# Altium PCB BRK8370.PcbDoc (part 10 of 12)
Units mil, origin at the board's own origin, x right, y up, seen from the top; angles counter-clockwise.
Board outline 8267.72 x 5708.66 mil, 6 copper layers (L1-TOP, L2-GND, L3-PWR, L4-PWR, L5-GND, L6-BOT), stack 68.606 mil thick; 319 components, 516 nets, 2008 pads, 1743 vias.
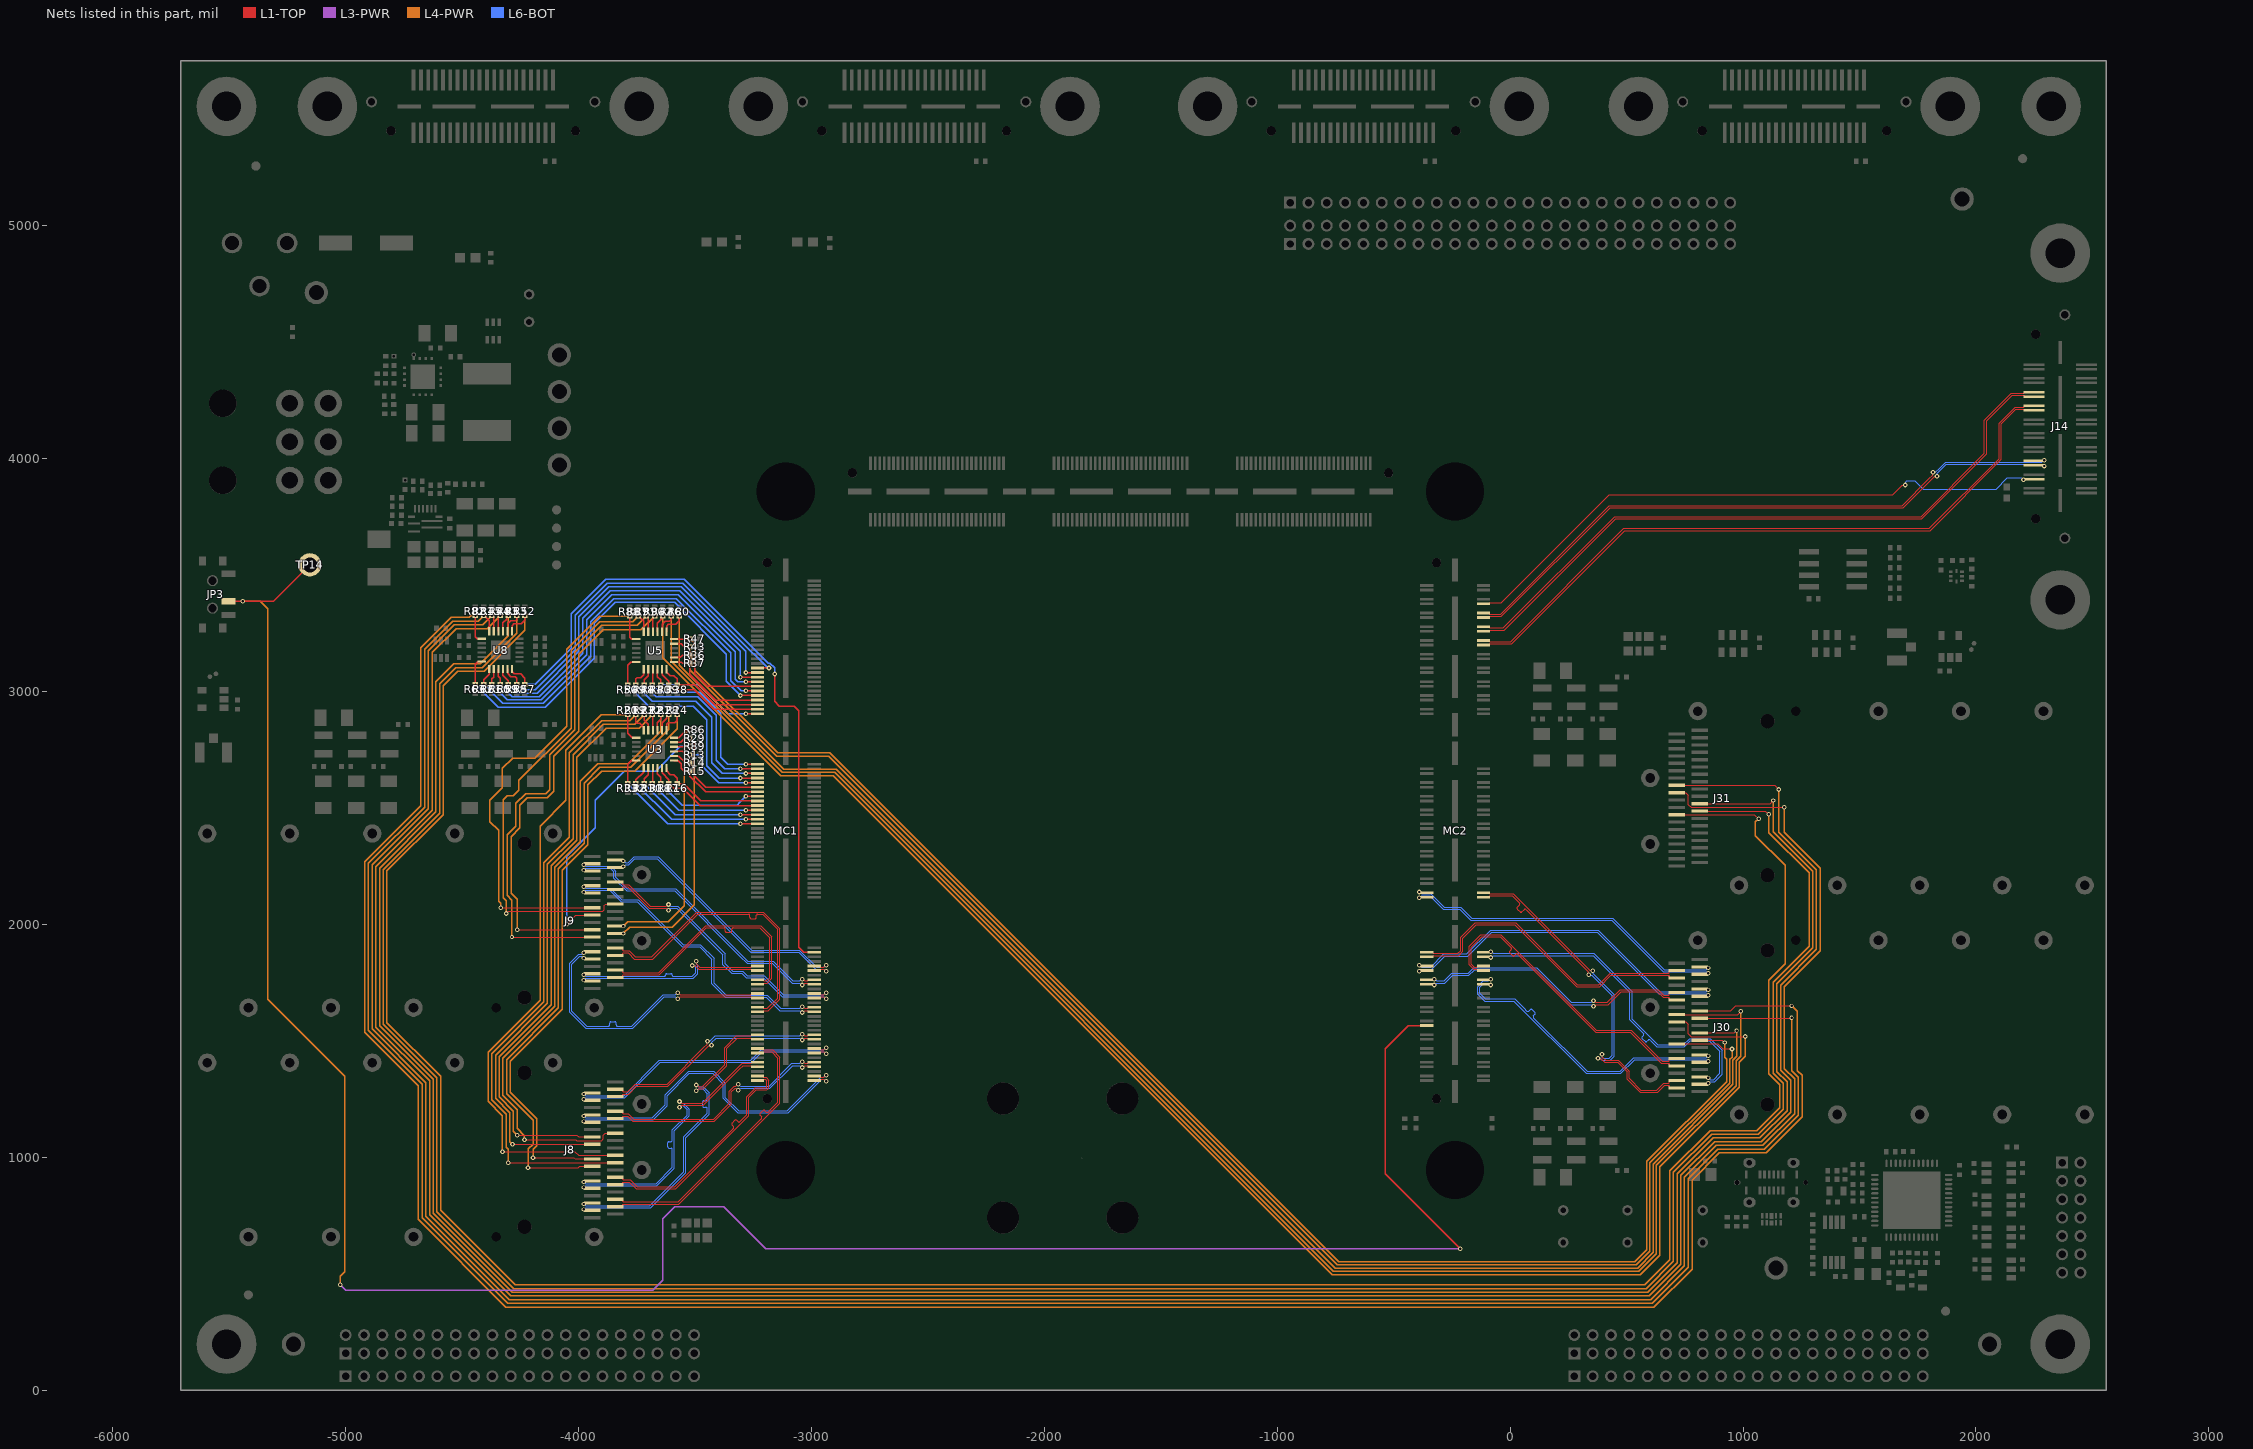
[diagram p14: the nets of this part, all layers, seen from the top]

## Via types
v1: diameter 20, hole 10, L1-TOP to L6-BOT, tented both sides, 957 vias
v2: diameter 18, hole 10, L1-TOP to L6-BOT, tented both sides, 786 vias

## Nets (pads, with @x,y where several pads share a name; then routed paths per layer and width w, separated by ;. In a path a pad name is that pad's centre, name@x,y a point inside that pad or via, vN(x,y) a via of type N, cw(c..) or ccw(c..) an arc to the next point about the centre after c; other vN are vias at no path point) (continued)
PORTE_TX0_P: J14.6 MC2.114 | length 2582.4
  L1-TOP w3.3: MC2.114@-114.57,3375.98 -91.93,3375.98 -86.59,3381.33 -70.57,3381.33 -61.42,3381.33 -37.43,3381.33 425.45,3844.21 1643.92,3844.21 1673.19,3873.48 1683.92,3884.21 1695.24,3884.21 v1(1696.85,3885.83)
  L6-BOT w3.3: v1(1696.85,3885.83) 1698.46,3887.44 1698.46,3898.75 1703.26,3903.55 1737.7,3903.55 1773.42,3867.83 2086.87,3867.83 2135.36,3916.32 2184.92,3916.32 2194.24,3916.32 2202.24,3908.32 v1(2204.53,3908.32)
PORTE_TX1_N: J14.12 MC2.112 | length 2691.1
  L1-TOP w3.3: MC2.112@-114.57,3336.61 -91.93,3336.61 -86.59,3331.27 -66.84,3331.27 -61.42,3331.27 -41.15,3331.27 425.66,3798.09 1683.49,3798.09 1800.53,3915.12 1813.89,3928.49 1813.89,3939.8 v1(1815.51,3941.41)
  L6-BOT w3.3: v1(1815.51,3941.41) 1817.12,3943.03 1828.44,3943.03 1841.8,3956.39 1869.78,3984.37 2184.92,3984.37 2283.61,3984.37 2291.61,3992.37 v1(2293.9,3992.37)
PORTE_TX1_P: J14.10 MC2.110 | length 2691.1
  L1-TOP w3.3: MC2.110@-114.57,3316.93 -91.93,3316.93 -86.59,3322.27 -70.57,3322.27 -61.42,3322.27 -37.43,3322.27 429.39,3789.09 1687.22,3789.09 1809.53,3911.39 1820.26,3922.12 1831.57,3922.12 v1(1833.19,3923.74)
  L6-BOT w3.3: v1(1833.19,3923.74) 1834.8,3925.35 1834.8,3936.66 1845.53,3947.39 1873.51,3975.37 2184.92,3975.37 2283.61,3975.37 2291.61,3967.37 v1(2293.9,3967.37)
PORTE_TX2_N: J14.32 MC2.108 | length 2868.5
  L1-TOP w3.3: MC2.108@-114.57,3277.56 -91.93,3277.56 -86.59,3272.22 -61.42,3272.22 -29.34,3272.22 449.28,3750.84 1764.25,3750.84 2036.56,4023.16 2036.56,4164.89 2151.32,4279.65 2184.92,4279.65 2185.34,4279.65 2204.7,4279.65 2210.04,4284.99 J14.32@2249.21,4284.99
PORTE_TX2_P: J14.30 MC2.106 | length 2868.5
  L1-TOP w3.3: MC2.106@-114.57,3257.87 -91.93,3257.87 -86.59,3263.22 -61.42,3263.22 -25.61,3263.22 453.01,3741.84 1767.97,3741.84 2045.56,4019.43 2045.56,4161.16 2155.04,4270.65 2184.92,4270.65 2189.07,4270.65 2204.7,4270.65 2210.04,4265.3 J14.30@2249.21,4265.3
PORTE_TX3_N: J14.28 MC2.104 | length 2874.8
  L1-TOP w3.3: MC2.104@-114.57,3218.5 -91.93,3218.5 -86.59,3213.16 -61.42,3213.16 2.15,3213.16 488.66,3699.66 1799.68,3699.66 2099.55,3999.53 2099.55,4151.95 2168.2,4220.59 2184.92,4220.59 2204.7,4220.59 2210.04,4225.93 J14.28@2249.21,4225.93
PORTE_TX3_P: J14.26 MC2.102 | length 2874.8
  L1-TOP w3.3: MC2.102@-114.57,3198.82 -91.93,3198.82 -86.59,3204.16 -61.42,3204.16 5.88,3204.16 492.38,3690.66 1803.41,3690.66 2108.55,3995.81 2108.55,4148.22 2171.93,4211.59 2184.92,4211.59 2204.7,4211.59 2210.04,4206.25 J14.26@2249.21,4206.25
PWR_EN: JP3.2 MC2.17 TP14.1 | length 9989.5
  L1-TOP w6: MC2.17@-357.87,1564.96 -436.57,1564.96 -536.84,1464.69 -536.84,928.23 v1(-214.92,606.3)
  L1-TOP w7: JP3.2@-5502.92,3386.84 v1(-5441.96,3386.84) -5310.01,3386.84 TP14.1@-5153.54,3543.31
  L3-PWR w6: v1(-5023.62,452.76) -5000,429.13 -3681.1,429.13 -3637.8,472.44 -3637.8,735.5 -3586.35,786.95 -3377.5,786.95 -3196.85,606.3 v1(-214.92,606.3)
  L4-PWR w6: v1(-5441.96,3386.84) -5367.15,3386.84 -5334.65,3354.33 -5334.65,1677.16 -5003.94,1346.46 -5003.94,507.87 -5023.62,488.19 v1(-5023.62,452.76)
QSFP_1_INT_B_3V3: J8.28 R20.1 U3.19 | length 2831.2
  L1-TOP w5: v1(-4326.77,1023.62) -4015.75,1023.62 -3999.24,1007.11 -3844.07,1007.11 J8.28@-3843.31,1007.87
  L1-TOP w6: v1(-3789.37,2899.61) -3789.37,2820.87 -3769.69,2801.18 U3.19@-3751.97,2801.18
  L4-PWR w6: v1(-4326.77,1023.62) -4326.77,1177.92 -4388.1,1239.25 -4388.1,1450.48 -4165.35,1673.23 -4165.35,2421.26 -4055.12,2531.5 -4055.12,2748.03 -3903.54,2899.61 v1(-3789.37,2899.61)
QSFP_1_INT_B_VIO: MC1.93 R33.1 U3.24 | length 755.8
  L1-TOP w6: v1(-3789.37,2604.33) -3789.37,2687.01 -3773.62,2702.76 U3.24@-3751.97,2702.76 ; v1(-3305.12,2431.1) MC1.93@-3231.89,2431.1
  L6-BOT w6: v1(-3789.37,2604.33) -3616.14,2431.1 v1(-3305.12,2431.1)
QSFP_1_LP_MODE_3V3: J8.31 R21.1 U3.15 | length 2705.5
  L1-TOP w5: v1(-4232.28,1074.8) -4011.81,1074.8 -4007.87,1070.87 -3901.57,1070.87 -3893.7,1078.74 -3893.7,1094.49 -3885.83,1102.36 J8.31@-3843.31,1102.36
  L1-TOP w6: U3.15@-3661.42,2832.68 -3661.42,2866.14 -3647.64,2879.92 v1(-3647.64,2899.61)
  L4-PWR w6: v1(-4232.28,1074.8) -4232.28,1092.83 -4263.78,1124.33 -4263.78,1204.01 -4325.11,1265.34 -4325.11,1424.39 -4102.36,1647.14 -4102.36,2244.21 -3992.13,2354.45 -3992.13,2614.17 -3917.32,2688.98 -3787.4,2688.98 -3647.64,2828.74 v1(-3647.64,2899.61)
QSFP_1_LP_MODE_VIO: MC1.105 R18.1 U3.4 | length 542.2
  L1-TOP w6: U3.4@-3661.42,2671.26 -3661.42,2645.67 -3647.64,2631.89 v1(-3647.64,2604.33) ; v1(-3281.5,2549.21) MC1.105@-3231.89,2549.21
  L6-BOT w6: v1(-3647.64,2604.33) -3555.12,2511.81 -3318.9,2511.81 -3307.09,2523.62 v1(-3281.5,2549.21)
QSFP_1_MODPRS_B_3V3: J8.27 R19.1 U3.18 | length 2826.6
  L1-TOP w5: v1(-4302.26,976) -4302.07,976.19 -3843.5,976.19 J8.27@-3843.31,976.38
  L1-TOP w6: v1(-3753.94,2899.61) -3753.94,2868.11 -3748.03,2862.2 -3737.01,2862.2 -3720.47,2845.67 U3.18@-3720.47,2832.68
  L4-PWR w6: v1(-4302.26,976) -4302.26,1033.43 -4311.02,1042.19 -4311.02,1184.44 -4372.36,1245.77 -4372.36,1443.96 -4149.61,1666.71 -4149.61,2263.78 -4039.37,2374.02 -4039.37,2736.22 -3901.57,2874.02 -3779.53,2874.02 v1(-3753.94,2899.61)
QSFP_1_MODPRS_B_VIO: MC1.95 R32.1 U3.1 | length 666.4
  L1-TOP w6: v1(-3753.94,2604.33) -3753.94,2620.08 -3720.47,2653.54 U3.1@-3720.47,2671.26 ; v1(-3281.5,2450.79) MC1.95@-3231.89,2450.79
  L6-BOT w6: v1(-3753.94,2604.33) -3600.39,2450.79 v1(-3281.5,2450.79)
QSFP_1_MODSEL_B_3V3: J8.8 R22.1 U3.16 | length 2585.2
  L1-TOP w5: v1(-4263.78,1094.49) -4007.87,1094.49 -4000,1086.61 J8.8@-3942.13,1086.61
  L1-TOP w6: v1(-3683.07,2899.61) -3681.1,2897.64 U3.16@-3681.1,2832.68
  L4-PWR w6: v1(-4263.78,1094.49) -4279.53,1110.24 -4279.53,1197.48 -4340.86,1258.82 -4340.86,1430.91 -4118.11,1653.66 -4118.11,2250.73 -4007.87,2360.97 -4007.87,2716.54 -3881.89,2842.52 -3740.16,2842.52 v1(-3683.07,2899.61)
QSFP_1_MODSEL_B_VIO: MC1.99 R30.1 U3.3 | length 566.2
  L1-TOP w6: v1(-3683.07,2604.33) -3681.1,2606.3 U3.3@-3681.1,2671.26 ; v1(-3281.5,2490.16) MC1.99@-3231.89,2490.16
  L6-BOT w6: v1(-3683.07,2604.33) -3568.9,2490.16 v1(-3281.5,2490.16)
QSFP_1_RESET_B_3V3: J8.9 R23.1 U3.17 | length 2633.1
  L1-TOP w5: v1(-4283.46,1055.12) J8.9@-3942.13,1055.12
  L1-TOP w6: v1(-3718.5,2899.61) -3718.5,2875.98 -3700.79,2858.27 U3.17@-3700.79,2832.68
  L4-PWR w6: v1(-4283.46,1055.12) -4295.28,1066.93 -4295.28,1190.96 -4356.61,1252.29 -4356.61,1437.43 -4133.86,1660.18 -4133.86,2257.26 -4023.62,2367.49 -4023.62,2728.35 -3893.7,2858.27 -3759.84,2858.27 v1(-3718.5,2899.61)
QSFP_1_RESET_B_VIO: MC1.97 R31.1 U3.2 | length 616.3
  L1-TOP w6: v1(-3718.5,2604.33) -3718.5,2624.02 -3700.79,2641.73 U3.2@-3700.79,2671.26 ; v1(-3305.12,2470.47) MC1.97@-3231.89,2470.47
  L6-BOT w6: v1(-3718.5,2604.33) -3584.65,2470.47 v1(-3305.12,2470.47)
QSFP_1_RX1_N: J8.18 MC1.21 | length 1359.2
  L1-TOP w3.3: v1(-3494.53,1309.97) -3492.25,1309.97 -3484.25,1301.97 -3468.1,1301.97 -3372.89,1397.17 -3372.89,1470.65 -3323.29,1520.25 -3307.09,1520.25 -3259.87,1520.25 -3254.53,1525.59 MC1.21@-3231.89,1525.59
  L6-BOT w3.3: v2(-3977.59,775.76) -3975.45,775.76 -3968.31,782.9 -3690.97,782.9 -3540.5,933.38 -3540.5,1083.14 -3438.69,1184.94 -3438.69,1276.84 -3463.82,1301.97 -3484.25,1301.97 -3492.25,1309.97 v1(-3494.53,1309.97)
QSFP_1_RX1_P: J8.17 MC1.19 | length 1359.2
  L1-TOP w3.3: v1(-3494.53,1284.97) -3492.25,1284.97 -3484.25,1292.97 -3464.37,1292.97 -3363.89,1393.44 -3363.89,1466.92 -3319.56,1511.25 -3307.09,1511.25 -3259.87,1511.25 -3254.53,1505.91 MC1.19@-3231.89,1505.91
  L6-BOT w3.3: v2(-3977.59,799.05) -3975.45,799.05 -3968.31,791.9 -3694.7,791.9 -3549.5,937.1 -3549.5,1086.87 -3447.69,1188.67 -3447.69,1206.92 -3447.69,1208.57 ccw(c-3453.35,1208.57) -3453.35,1214.23 -3461.8,1214.23 cw(c-3461.8,1219.89) -3467.46,1219.89 -3467.46,1236.87 cw(c-3461.8,1236.87) -3461.8,1242.53 -3453.35,1242.53 ccw(c-3453.35,1248.19) -3447.69,1248.19 -3447.69,1261 -3447.69,1273.12 -3467.54,1292.97 -3484.25,1292.97 -3492.25,1284.97 v1(-3494.53,1284.97)
QSFP_1_RX2_N: J8.21 MC1.15 | length 1203.4
  L1-TOP w3.3: J8.21@-3843.31,787.4 -3814.76,787.4 -3809.52,792.64 -3809.52,796.72 -3807.59,798.65 -3568.92,798.65 -3135.54,1232.03 -3135.54,1291.34 -3135.54,1429.39 -3167.35,1461.19 -3203.91,1461.19 -3209.25,1466.54 MC1.15@-3231.89,1466.54
QSFP_1_RX2_P: J8.22 MC1.13 | length 1203.4
  L1-TOP w3.3: J8.22@-3843.31,818.9 -3814.76,818.9 -3809.52,813.66 -3809.52,809.58 -3807.59,807.65 -3572.65,807.65 -3215.74,1164.56 -3214.57,1165.73 ccw(c-3218.58,1169.73) -3214.57,1173.73 -3220.55,1179.71 cw(c-3216.55,1183.71) -3220.55,1187.71 -3208.54,1199.72 cw(c-3204.54,1195.71) -3200.54,1199.72 -3194.56,1193.74 ccw(c-3190.56,1197.74) -3186.56,1193.74 -3176.37,1203.93 -3144.54,1235.75 -3144.54,1291.34 -3144.54,1425.66 -3171.07,1452.19 -3203.91,1452.19 -3209.25,1446.85 MC1.13@-3231.89,1446.85
QSFP_1_RX3_N: J8.15 MC1.9 | length 1169.9
  L1-TOP w3.3: v1(-3566.93,1239.16) -3564.65,1239.16 -3556.65,1231.16 -3468.2,1231.16 -3307.09,1392.27 -3297.22,1402.14 -3259.87,1402.14 -3254.53,1407.48 MC1.9@-3231.89,1407.48
  L6-BOT w3.3: v2(-3977.59,870.24) -3975.45,870.24 -3968.31,877.39 -3663.41,877.39 -3588.3,952.5 -3588.3,1114.08 -3525.31,1177.07 -3525.31,1206.41 -3550.06,1231.16 -3556.65,1231.16 -3564.65,1239.16 v1(-3566.93,1239.16)
QSFP_1_RX3_P: J8.14 MC1.7 | length 1175.2
  L1-TOP w3.3: v1(-3566.93,1214.16) -3564.65,1214.16 -3556.65,1222.16 -3464.47,1222.16 -3307.09,1379.54 -3293.49,1393.14 -3259.87,1393.14 -3254.53,1387.8 MC1.7@-3231.89,1387.8 MC1.7@-3235.6,1391.5
  L6-BOT w3.3: v2(-3977.59,893.54) -3975.45,893.54 -3968.31,886.39 -3667.14,886.39 -3597.3,956.23 -3597.3,1031.5 -3597.3,1033.15 ccw(c-3602.96,1033.15) -3602.96,1038.81 -3611.41,1038.81 cw(c-3611.41,1044.47) -3617.07,1044.47 -3617.07,1061.45 cw(c-3611.41,1061.45) -3611.41,1067.11 -3602.96,1067.11 ccw(c-3602.96,1072.77) -3597.3,1072.77 -3597.3,1102.36 -3597.3,1117.81 -3534.31,1180.8 -3534.31,1202.68 -3553.79,1222.16 -3556.65,1222.16 -3564.65,1214.16 v1(-3566.93,1214.16)
QSFP_1_RX4_N: J8.24 MC1.3 | length 995.9
  L1-TOP w3.3: J8.24@-3843.31,881.89 -3814.76,881.89 -3809.52,887.13 -3809.52,891.2 -3807.59,893.14 -3781.47,893.14 -3752.23,863.89 -3582.42,863.89 -3268.84,1177.47 -3268.84,1256.37 -3236.88,1288.33 -3191.48,1288.33 -3188.48,1291.34 -3182.62,1297.19 -3182.62,1331.04 -3194.67,1343.08 -3203.91,1343.08 -3209.25,1348.43 MC1.3@-3231.89,1348.43
QSFP_1_RX4_P: J8.25 MC1.1 | length 995.9
  L1-TOP w3.3: J8.25@-3843.31,913.39 -3814.76,913.39 -3809.52,908.15 -3809.52,904.07 -3807.59,902.14 -3777.74,902.14 -3748.5,872.89 -3586.15,872.89 -3336.19,1122.85 -3335.02,1124.02 ccw(c-3339.02,1128.02) -3335.02,1132.02 -3341,1138 cw(c-3337,1142) -3341,1146 -3328.99,1158.01 cw(c-3324.99,1154.01) -3320.99,1158.01 -3315.01,1152.03 ccw(c-3311.01,1156.03) -3307.01,1152.03 -3294.48,1164.56 -3277.84,1181.2 -3277.84,1260.1 -3246.6,1291.34 -3240.61,1297.33 -3195.21,1297.33 -3191.62,1300.92 -3191.62,1327.31 -3198.4,1334.08 -3203.91,1334.08 -3209.25,1328.74 MC1.1@-3231.89,1328.74
QSFP_1_SCL_3V3: J8.11 R24.1 U3.13 | length 2693.3
  L1-TOP w5: v1(-4195.48,996.99) -4020.03,996.99 -4015.17,992.13 J8.11@-3942.13,992.13
  L1-TOP w6: U3.13@-3622.05,2832.68 -3622.05,2858.27 -3614.17,2866.14 -3586.61,2866.14 -3576.77,2875.98 v1(-3576.77,2899.61)
  L4-PWR w6: v1(-4195.48,996.99) -4195.48,1032.96 -4180.33,1048.11 -4180.33,1164.58 -4293.98,1278.23 -4293.98,1411.49 -4071.23,1634.24 -4071.23,2231.32 -3961,2341.55 -3961,2598.06 -3901.57,2657.48 -3759.84,2657.48 -3576.77,2840.55 v1(-3576.77,2899.61)
QSFP_1_SCL_VIO: MC1.103 R16.1 U3.6 | length 470.3
  L1-TOP w6: U3.6@-3622.05,2671.26 -3622.05,2658.27 -3605.51,2641.73 -3590.55,2641.73 -3576.77,2627.95 R16.1@-3576.77,2604.33 -3549.21,2604.33 -3474.41,2529.53 MC1.103@-3231.89,2529.53
QSFP_1_SDA_3V3: J8.12 R28.1 U3.14 | length 2725.1
  L1-TOP w5: v1(-4216.93,954.78) -4216.69,955.01 -4001.68,955.01 -3996.06,960.63 J8.12@-3942.13,960.63
  L1-TOP w6: U3.14@-3641.73,2832.68 -3641.73,2864.27 -3620.49,2885.51 -3620.49,2892.76 -3613.65,2899.61 v1(-3612.2,2899.61)
  L4-PWR w6: v1(-4216.93,954.78) -4216.93,1035.04 -4195.71,1056.26 -4195.71,1158.21 -4309.36,1271.86 -4309.36,1417.86 -4086.61,1640.61 -4086.61,2237.69 -3976.38,2347.92 -3976.38,2606.3 -3909.45,2673.23 -3775.59,2673.23 -3612.2,2836.61 v1(-3612.2,2899.61)
QSFP_1_SDA_VIO: MC1.101 R17.1 U3.5 | length 498.6
  L1-TOP w6: U3.5@-3641.73,2671.26 -3641.73,2649.61 -3612.2,2620.08 R17.1@-3612.2,2604.33 -3610.24,2604.33 -3590.98,2585.08 -3552.21,2585.08 -3476.98,2509.84 MC1.101@-3231.89,2509.84
QSFP_1_TX1_N: J8.37 MC1.22 | length 976.7
  L1-TOP w3.3: J8.37@-3843.31,1291.34 -3814.76,1291.34 -3809.52,1286.1 -3809.52,1282.02 -3807.59,1280.09 -3789.18,1280.09 -3756,1313.27 -3620.22,1313.27 -3461.79,1471.7 -3448.43,1485.06 -3448.43,1496.38 v1(-3446.81,1497.99) ; v1(-3040.16,1528.25) -3037.87,1528.25 -3029.87,1520.25 -3016.56,1520.25 -3011.22,1525.59 MC1.22@-2988.58,1525.59
  L6-BOT w3.3: v1(-3446.81,1497.99) -3445.2,1499.61 -3433.88,1499.61 -3413.24,1520.25 -3307.09,1520.25 -3050.44,1520.25 -3042.44,1528.25 v1(-3040.16,1528.25)
QSFP_1_TX1_P: J8.36 MC1.20 | length 976.7
  L1-TOP w3.3: J8.36@-3843.31,1259.84 -3814.76,1259.84 -3809.52,1265.08 -3809.52,1269.16 -3807.59,1271.09 -3785.46,1271.09 -3752.27,1304.27 -3616.49,1304.27 -3452.79,1467.97 -3442.06,1478.7 -3430.75,1478.7 v1(-3429.13,1480.32) ; v1(-3040.16,1503.25) -3037.87,1503.25 -3029.87,1511.25 -3016.56,1511.25 -3011.22,1505.91 MC1.20@-2988.58,1505.91
  L6-BOT w3.3: v1(-3429.13,1480.32) -3427.52,1481.93 -3427.52,1493.24 -3409.51,1511.25 -3307.09,1511.25 -3050.44,1511.25 -3042.44,1503.25 v1(-3040.16,1503.25)
QSFP_1_TX2_N: J8.2 MC1.16 | length 1185.5
  L1-TOP w3.3: MC1.16@-2988.58,1466.54 -2965.95,1466.54 -2960.6,1461.19 -2953.88,1461.19 -2947.29,1461.19 -2939.29,1469.19 v1(-2937.01,1469.19)
  L6-BOT w3.3: v2(-3977.59,1271.49) -3975.45,1271.49 -3968.31,1264.34 -3804.93,1264.34 -3653.08,1416.2 -3307.09,1416.2 -3260.52,1416.2 -3215.53,1461.19 -2947.29,1461.19 -2939.29,1469.19 v1(-2937.01,1469.19)
QSFP_1_TX2_P: J8.3 MC1.14 | length 1185.5
  L1-TOP w3.3: MC1.14@-2988.58,1446.85 -2965.94,1446.85 -2960.6,1452.19 -2950.15,1452.19 -2947.29,1452.19 -2939.29,1444.19 v1(-2937.01,1444.19)
  L6-BOT w3.3: v2(-3977.59,1248.2) -3975.45,1248.2 -3968.31,1255.34 -3801.2,1255.34 -3649.35,1407.2 -3307.09,1407.2 -3256.8,1407.2 -3211.8,1452.19 -2947.29,1452.19 -2939.29,1444.19 v1(-2937.01,1444.19)
QSFP_1_TX3_N: J8.34 MC1.10 | length 1015.7
  L1-TOP w3.3: J8.34@-3843.31,1196.85 -3814.76,1196.85 -3809.52,1191.61 -3809.52,1187.54 -3807.59,1185.6 -3785.74,1185.6 -3763.8,1163.67 -3420.34,1163.67 -3352.72,1231.29 -3352.72,1283.52 -3331.83,1304.4 -3325.24,1304.4 -3317.24,1312.4 v1(-3314.96,1312.4) ; v1(-3040.16,1410.14) -3037.87,1410.14 -3029.87,1402.14 -3016.56,1402.14 -3011.22,1407.48 MC1.10@-2988.58,1407.48
  L6-BOT w3.3: v1(-3314.96,1312.4) -3312.68,1312.4 -3307.09,1306.81 -3304.68,1304.4 -3182.36,1304.4 -3084.62,1402.14 -3050.44,1402.14 -3042.44,1410.14 v1(-3040.16,1410.14)
QSFP_1_TX3_P: J8.33 MC1.8 | length 1015.7
  L1-TOP w3.3: J8.33@-3843.31,1165.35 -3814.76,1165.35 -3809.52,1170.59 -3809.52,1174.67 -3807.59,1176.6 -3789.47,1176.6 -3767.53,1154.67 -3416.62,1154.67 -3343.72,1227.57 -3343.72,1279.79 -3328.1,1295.4 -3325.24,1295.4 -3317.24,1287.4 v1(-3314.96,1287.4) ; v1(-3040.16,1385.14) -3037.87,1385.14 -3029.87,1393.14 -3016.56,1393.14 -3011.22,1387.8 MC1.8@-2988.58,1387.8
  L6-BOT w3.3: v1(-3314.96,1287.4) -3312.68,1287.4 -3307.09,1292.99 -3304.68,1295.4 -3178.63,1295.4 -3080.89,1393.14 -3050.44,1393.14 -3042.44,1385.14 v1(-3040.16,1385.14)
QSFP_1_TX4_N: J8.5 MC1.4 | length 1377.1
  L1-TOP w3.3: MC1.4@-2988.58,1348.43 -2965.94,1348.43 -2960.6,1343.08 -2947.29,1343.08 -2939.29,1351.08 v1(-2937.01,1351.08)
  L6-BOT w3.3: v2(-3977.59,1177) -3975.45,1177 -3968.31,1169.85 -3682.89,1169.85 -3628.24,1224.5 -3628.24,1267.97 -3527.82,1368.39 -3420.16,1368.39 -3369.47,1317.71 -3369.47,1256 -3313.14,1199.66 -3103.72,1199.66 -3012.04,1291.34 -2960.3,1343.08 -2947.29,1343.08 -2939.29,1351.08 v1(-2937.01,1351.08)
QSFP_1_TX4_P: J8.6 MC1.2 | length 1377.1
  L1-TOP w3.3: MC1.2@-2988.58,1328.74 -2965.94,1328.74 -2960.6,1334.08 -2947.29,1334.08 -2939.29,1326.08 v1(-2937.01,1326.08)
  L6-BOT w3.3: v2(-3977.59,1153.71) -3975.45,1153.71 -3968.31,1160.85 -3679.16,1160.85 -3619.24,1220.78 -3619.24,1264.25 -3524.09,1359.39 -3423.88,1359.39 -3378.47,1313.98 -3378.47,1252.27 -3316.86,1190.66 -3099.99,1190.66 -2999.31,1291.34 -2956.57,1334.08 -2947.29,1334.08 -2939.29,1326.08 v1(-2937.01,1326.08)
QSFP_2_INT_B_3V3: J9.28 R86.1 U3.12 | length 1145.7
  L1-TOP w6: U3.12@-3590.55,2801.18 -3568.9,2801.18 -3535.43,2834.65 v1(-3521.65,2834.65)
  L4-PWR w6: v2(-3807.84,1992.13) -3788.16,2011.81 -3614.17,2011.81 -3547.24,2078.74 -3547.24,2809.06 v1(-3521.65,2834.65)
QSFP_2_INT_B_VIO: MC1.107 R15.1 U3.7 | length 438.3
  L1-TOP w6: U3.7@-3590.55,2702.76 -3572.83,2702.76 -3559.06,2688.98 -3559.06,2669.29 -3547.24,2657.48 R15.1@-3521.65,2657.48 -3521.65,2635.83 -3454.72,2568.9 MC1.107@-3231.89,2568.9
QSFP_2_LP_MODE_3V3: J9.31 R87.1 U5.18 | length 2195.2
  L1-TOP w5: v1(-4310.58,2045.91) -4301.37,2055.12 -3896.27,2055.12 -3889.76,2061.62 -3889.76,2080.62 -3883.77,2086.61 J9.31@-3843.31,2086.61
  L1-TOP w6: v1(-3744.09,3322.83) -3742.13,3322.83 -3720.47,3301.18 U5.18@-3720.47,3255.91
  L4-PWR w6: v1(-4310.58,2045.91) -4310.58,2100.55 -4324.22,2114.19 -4324.22,2534.05 -4307.09,2551.18 -4279.53,2551.18 -4255.91,2574.8 -4255.91,2617.83 -4031.69,2842.04 -4031.69,3176.97 -3909.45,3299.21 -3767.72,3299.21 v1(-3744.09,3322.83)
QSFP_2_LP_MODE_VIO: MC1.115 R49.1 U5.1 | length 884.7
  L1-TOP w6: v1(-3753.94,3027.56) -3753.94,3053.15 -3748.03,3059.06 -3732.28,3059.06 -3720.47,3070.87 U5.1@-3720.47,3094.49 ; v1(-3281.5,2647.64) MC1.115@-3231.89,2647.64
  L6-BOT w6: v1(-3753.94,3027.56) -3683.07,2956.69 -3496.06,2956.69 -3429.13,2889.76 -3429.13,2692.91 -3383.86,2647.64 v1(-3281.5,2647.64)
QSFP_2_MODPRS_B_3V3: J9.27 R29.1 U3.11 | length 1155.9
  L1-TOP w6: U3.11@-3590.55,2781.5 -3561.02,2781.5 -3543.31,2799.21 v1(-3521.65,2799.21)
  L4-PWR w6: v2(-3807.84,1960.63) -3780.28,1988.19 -3598.43,1988.19 -3502.3,2084.31 -3502.3,2779.86 v1(-3521.65,2799.21)
QSFP_2_MODPRS_B_VIO: MC1.109 R14.1 U3.8 | length 434
  L1-TOP w6: U3.8@-3590.55,2722.44 -3568.9,2722.44 -3539.37,2692.91 R14.1@-3521.65,2692.91 ; R14.1@-3521.65,2690.94 -3501.74,2671.03 -3501.74,2635.6 -3454.72,2588.58 MC1.109@-3231.89,2588.58
QSFP_2_MODSEL_B_3V3: J9.8 R88.1 U5.19 | length 2166.4
  L1-TOP w5: v2(-4334.65,2070.87) J9.8@-3942.13,2070.87
  L1-TOP w6: v1(-3779.53,3322.83) -3779.53,3232.28 -3771.65,3224.41 U5.19@-3751.97,3224.41
  L4-PWR w6: v2(-4334.65,2070.87) -4334.65,2089.18 -4343.9,2098.44 -4343.9,2402.96 -4381.89,2440.94 -4381.89,2531.5 -4326.77,2586.61 -4326.77,2669.29 -4283.46,2712.6 -4188.98,2712.6 -4051.38,2850.2 -4051.38,3180.9 -3909.45,3322.83 v1(-3779.53,3322.83)
QSFP_2_MODSEL_B_VIO: MC1.113 R50.1 U5.24 | length 966.1
  L1-TOP w6: v1(-3789.37,3027.56) -3789.37,3112.2 -3775.59,3125.98 U5.24@-3751.97,3125.98 ; v1(-3305.12,2627.95) MC1.113@-3231.89,2627.95
  L6-BOT w6: v1(-3789.37,3027.56) -3698.82,2937.01 -3507.87,2937.01 -3448.82,2877.95 -3448.82,2681.1 -3395.67,2627.95 v1(-3305.12,2627.95)
QSFP_2_RESET_B_3V3: J9.9 R89.1 U3.10 | length 1283.6
  L1-TOP w5: v1(-4051.18,2000) -4011.81,2039.37 J9.9@-3942.13,2039.37 J9.9@-3944.09,2037.4
  L1-TOP w6: U3.10@-3590.55,2761.81 -3523.62,2761.81 v1(-3521.65,2763.78)
  L6-BOT w6: v1(-4051.18,2000) -4051.18,2291.34 -3929.13,2413.39 -3929.13,2531.5 -3803.15,2657.48 -3669.29,2657.48 -3562.99,2763.78 v1(-3521.65,2763.78)
QSFP_2_RESET_B_VIO: MC1.111 R13.1 U3.9 | length 434.2
  L1-TOP w6: U3.9@-3590.55,2742.13 -3553.15,2742.13 -3539.37,2728.35 v1(-3521.65,2728.35) ; v1(-3281.5,2608.27) MC1.111@-3231.89,2608.27
  L6-BOT w6: v1(-3521.65,2728.35) -3484.25,2728.35 -3464.57,2708.66 -3464.57,2674.43 -3398.41,2608.27 v1(-3281.5,2608.27)
QSFP_2_RX1_N: J9.18 MC1.51 | length 838.9
  L1-TOP w3.3: v1(-3494.13,1840.51) -3492.52,1838.9 -3492.52,1827.58 -3480.46,1815.52 -3307.09,1815.52 -3259.87,1815.52 -3254.53,1820.87 MC1.51@-3231.89,1820.87
  L6-BOT w3.3: v2(-3977.59,1760.01) -3975.45,1760.01 -3968.31,1767.15 -3507.54,1767.15 -3487.5,1787.19 -3487.5,1822.57 -3492.52,1827.58 -3492.52,1838.9 v1(-3494.13,1840.51)
QSFP_2_RX1_P: J9.17 MC1.49 | length 838.9
  L1-TOP w3.3: v1(-3511.81,1822.83) -3510.2,1821.22 -3498.88,1821.22 -3484.19,1806.52 -3307.09,1806.52 -3259.87,1806.52 -3254.53,1801.18 MC1.49@-3231.89,1801.18
  L6-BOT w3.3: v2(-3977.59,1783.3) -3975.45,1783.3 -3968.31,1776.15 -3633.86,1776.15 -3632.21,1776.15 ccw(c-3632.21,1781.81) -3626.55,1781.81 -3626.55,1782.81 cw(c-3620.89,1782.81) -3620.89,1788.47 -3603.91,1788.47 cw(c-3603.91,1782.81) -3598.25,1782.81 -3598.25,1781.81 ccw(c-3592.59,1781.81) -3592.59,1776.15 -3562.99,1776.15 -3511.27,1776.15 -3496.5,1790.92 -3496.5,1818.84 -3498.88,1821.22 -3510.2,1821.22 v1(-3511.81,1822.83)
QSFP_2_RX2_N: J9.21 MC1.45 | length 1034.3
  L1-TOP w3.3: J9.21@-3843.31,1771.65 -3814.76,1771.65 -3809.52,1776.89 -3809.52,1780.97 -3807.59,1782.9 -3652.85,1782.9 -3451.17,1984.59 -3405.51,1984.59 -3375.56,1984.59 cw(c-3375.56,1978.93) -3369.9,1978.93 -3369.9,1970.48 ccw(c-3364.24,1970.48) -3364.24,1964.82 -3347.26,1964.82 ccw(c-3347.26,1970.48) -3341.6,1970.48 -3341.6,1978.93 cw(c-3335.94,1978.93) -3335.94,1984.59 -3313.24,1984.59 -3307.09,1984.59 -3221.08,1984.59 -3179.21,1942.72 -3179.21,1771.3 -3194.04,1756.47 -3203.91,1756.47 -3209.25,1761.81 MC1.45@-3231.89,1761.81
QSFP_2_RX2_P: J9.22 MC1.43 | length 1034.3
  L1-TOP w3.3: J9.22@-3843.31,1803.15 -3814.76,1803.15 -3809.52,1797.91 -3809.52,1793.83 -3807.59,1791.9 -3656.58,1791.9 -3454.9,1993.59 -3307.09,1993.59 -3217.35,1993.59 -3170.21,1946.44 -3170.21,1767.57 -3190.31,1747.47 -3203.91,1747.47 -3209.25,1742.13 MC1.43@-3231.89,1742.13
QSFP_2_RX3_N: J9.15 MC1.39 | length 1188.4
  L1-TOP w3.3: v1(-3574.8,1705.41) -3572.52,1705.41 -3564.52,1697.41 -3307.09,1697.41 -3279.62,1697.41 -3259.87,1697.41 -3254.53,1702.76 MC1.39@-3231.89,1702.76
  L6-BOT w3.3: v2(-3977.59,1854.5) -3979.73,1854.5 -3986.87,1861.64 -3994.95,1861.64 -4028.68,1827.9 -4028.68,1625.52 -3965.03,1561.87 -3905.19,1561.87 -3872.72,1561.87 ccw(c-3872.72,1567.53) -3867.06,1567.53 -3867.06,1575.98 cw(c-3861.4,1575.98) -3861.4,1581.64 -3844.42,1581.64 cw(c-3844.42,1575.98) -3838.76,1575.98 -3838.76,1567.53 ccw(c-3833.1,1567.53) -3833.1,1561.87 -3803.15,1561.87 -3771.19,1561.87 -3635.64,1697.41 -3585.09,1697.41 -3577.09,1705.41 v1(-3574.8,1705.41)
QSFP_2_RX3_P: J9.14 MC1.37 | length 1188.4
  L1-TOP w3.3: v1(-3574.8,1680.41) -3572.52,1680.41 -3564.52,1688.41 -3307.09,1688.41 -3275.89,1688.41 -3259.87,1688.41 -3254.53,1683.07 MC1.37@-3231.89,1683.07
  L6-BOT w3.3: v2(-3977.59,1877.79) -3979.73,1877.79 -3986.87,1870.64 -3998.67,1870.64 -4037.68,1831.63 -4037.68,1621.79 -3968.76,1552.87 -3767.46,1552.87 -3631.91,1688.41 -3585.09,1688.41 -3577.09,1680.41 v1(-3574.8,1680.41)
QSFP_2_RX4_N: J9.24 MC1.33 | length 1257.1
  L1-TOP w3.3: J9.24@-3843.31,1866.14 -3814.76,1866.14 -3809.52,1871.38 -3809.52,1875.46 -3807.59,1877.39 -3787.25,1877.39 -3760.35,1850.49 -3682.43,1850.49 -3489.35,2043.58 -3307.09,2043.58 -3300.2,2043.58 -3270.25,2043.58 cw(c-3270.25,2037.92) -3264.59,2037.92 -3264.59,2029.47 ccw(c-3258.93,2029.47) -3258.93,2023.81 -3241.95,2023.81 ccw(c-3241.95,2029.47) -3236.29,2029.47 -3236.29,2037.92 cw(c-3230.63,2037.92) -3230.63,2043.58 -3218.6,2043.58 -3210.14,2043.58 -3144.54,1977.99 -3144.54,1682.68 -3188.86,1638.36 -3203.91,1638.36 -3209.25,1643.7 MC1.33@-3231.89,1643.7
QSFP_2_RX4_P: J9.25 MC1.31 | length 1257.1
  L1-TOP w3.3: J9.25@-3843.31,1897.64 -3814.76,1897.64 -3809.52,1892.4 -3809.52,1888.32 -3807.59,1886.39 -3783.52,1886.39 -3756.62,1859.49 -3686.16,1859.49 -3493.07,2052.58 -3307.09,2052.58 -3206.41,2052.58 -3135.54,1981.71 -3135.54,1678.95 -3185.14,1629.36 -3203.91,1629.36 -3209.25,1624.02 MC1.31@-3231.89,1624.02
QSFP_2_SCL_3V3: J9.11 R90.1 U5.16 | length 2149.3
  L1-TOP w5: v2(-4263.25,1976.34) J9.11@-3942.13,1976.38
  L1-TOP w6: U5.16@-3681.1,3255.91 -3681.1,3315.99 -3674.26,3322.83 v1(-3673.23,3322.83)
  L4-PWR w6: v2(-4263.25,1976.34) -4263.25,2108.33 -4288.79,2133.87 -4288.79,2376.57 -4251.97,2413.39 -4251.97,2511.81 -4220.47,2543.31 -4133.86,2543.31 -4106.3,2570.87 -4106.3,2720.59 -3998.57,2828.32 -3998.57,3158.91 -3893.7,3263.78 -3732.28,3263.78 v1(-3673.23,3322.83)
QSFP_2_SCL_VIO: MC1.119 R41.1 U5.3 | length 770.7
  L1-TOP w6: v1(-3683.07,3027.56) -3681.1,3029.53 U5.3@-3681.1,3094.49 ; v1(-3281.5,2687.01) MC1.119@-3231.89,2687.01
  L6-BOT w6: v1(-3683.07,3027.56) -3651.57,2996.06 -3480.31,2996.06 -3389.76,2905.51 -3389.76,2716.54 -3360.24,2687.01 v1(-3281.5,2687.01)
QSFP_2_SDA_3V3: J9.12 R91.1 U5.17 | length 2189
  L1-TOP w5: v2(-4286.54,1945.41) -4286.28,1945.14 -3942.39,1945.14 J9.12@-3942.13,1944.88
  L1-TOP w6: v1(-3708.66,3322.83) -3707.63,3322.83 -3700.79,3315.99 U5.17@-3700.79,3255.91
  L4-PWR w6: v2(-4286.54,1945.41) -4286.54,2104.07 -4306.16,2123.69 -4306.16,2383.77 -4269.35,2420.58 -4269.35,2519.01 -4227.67,2560.69 -4141.06,2560.69 -4123.68,2578.06 -4123.68,2727.79 -4015.95,2835.52 -4015.95,3168.77 -3901.25,3283.46 -3748.03,3283.46 v1(-3708.66,3322.83)
QSFP_2_SDA_VIO: MC1.117 R48.1 U5.2 | length 823.1
  L1-TOP w6: v1(-3718.5,3027.56) -3718.5,3049.21 -3700.79,3066.93 U5.2@-3700.79,3094.49 ; v1(-3305.12,2667.32) MC1.117@-3231.89,2667.32
  L6-BOT w6: v1(-3718.5,3027.56) -3667.32,2976.38 -3488.19,2976.38 -3409.45,2897.64 -3409.45,2704.72 -3372.05,2667.32 v1(-3305.12,2667.32)
QSFP_2_TX1_N: J9.37 MC1.52 | length 1141.5
  L1-TOP w3.3: MC1.52@-2988.58,1820.87 -2965.94,1820.87 -2960.6,1815.52 -2947.29,1815.52 -2939.29,1823.52 v1(-2937.01,1823.52)
  L6-BOT w3.3: v2(-3807.84,2271.49) -3805.71,2271.49 -3798.56,2264.34 -3787.47,2264.34 -3761.6,2290.21 -3657.78,2290.21 -3307.09,1939.52 -3256.21,1888.64 -3051.49,1888.64 -2978.37,1815.52 -2947.29,1815.52 -2939.29,1823.52 v1(-2937.01,1823.52)
QSFP_2_TX1_P: J9.36 MC1.50 | length 1141.5
  L1-TOP w3.3: MC1.50@-2988.58,1801.18 -2965.94,1801.18 -2960.6,1806.52 -2947.29,1806.52 -2939.29,1798.52 v1(-2937.01,1798.52)
  L6-BOT w3.3: v2(-3807.84,2248.2) -3805.71,2248.2 -3798.56,2255.34 -3783.75,2255.34 -3757.87,2281.21 -3661.51,2281.21 -3307.09,1926.79 -3259.94,1879.64 -3055.21,1879.64 -2982.1,1806.52 -2947.29,1806.52 -2939.29,1798.52 v1(-2937.01,1798.52)
QSFP_2_TX2_N: J9.2 MC1.46 | length 1220.1
  L1-TOP w3.3: v1(-3040.16,1764.47) -3037.87,1764.47 -3029.87,1756.47 -3024.61,1756.47 -3016.56,1756.47 -3011.22,1761.81 MC1.46@-2988.58,1761.81
  L6-BOT w3.3: v2(-3977.59,2255.74) -3975.45,2255.74 -3968.31,2248.59 -3860.26,2248.59 -3840.27,2228.6 -3840.27,2202.16 -3790.53,2152.42 -3583.7,2152.42 -3307.09,1875.8 -3272.68,1841.39 -3164.46,1841.39 -3079.53,1756.47 -3050.44,1756.47 -3042.44,1764.47 v1(-3040.16,1764.47)
QSFP_2_TX2_P: J9.3 MC1.44 | length 1220.1
  L1-TOP w3.3: v1(-3040.16,1739.47) -3037.87,1739.47 -3029.87,1747.47 -3020.88,1747.47 -3016.56,1747.47 -3011.22,1742.13 MC1.44@-2988.58,1742.13
  L6-BOT w3.3: v2(-3977.59,2232.45) -3975.45,2232.45 -3968.31,2239.59 -3863.99,2239.59 -3849.27,2224.88 -3849.27,2198.43 -3794.25,2143.42 -3587.43,2143.42 -3307.09,1863.07 -3276.41,1832.39 -3168.19,1832.39 -3083.26,1747.47 -3050.44,1747.47 -3042.44,1739.47 v1(-3040.16,1739.47)
QSFP_2_TX3_N: J9.34 MC1.40 | length 1201.4
  L1-TOP w3.3: J9.34@-3843.31,2181.1 -3814.76,2181.1 -3809.52,2175.86 -3809.52,2171.79 -3807.59,2169.85 -3785.64,2169.85 -3692.84,2077.05 -3624.46,2077.05 -3616.46,2085.05 v1(-3614.17,2085.05) ; MC1.40@-2988.58,1702.76 -2965.94,1702.76 -2960.6,1697.41 -2947.29,1697.41 -2939.29,1705.41 v1(-2937.01,1705.41)
  L6-BOT w3.3: v1(-3614.17,2085.05) -3611.89,2085.05 -3603.89,2077.05 -3574.71,2077.05 -3371.2,1873.55 -3371.2,1830.24 -3339.05,1798.09 -3307.09,1798.09 -3295.74,1798.09 -3276.06,1778.4 -3202.39,1778.4 -3121.4,1697.41 -2947.29,1697.41 -2939.29,1705.41 v1(-2937.01,1705.41)
QSFP_2_TX3_P: J9.33 MC1.38 | length 1201.4
  L1-TOP w3.3: J9.33@-3843.31,2149.61 -3814.76,2149.61 -3809.52,2154.85 -3809.52,2158.92 -3807.59,2160.85 -3789.36,2160.85 -3696.56,2068.05 -3624.46,2068.05 -3616.46,2060.05 v1(-3614.17,2060.05) ; MC1.38@-2988.58,1683.07 -2965.94,1683.07 -2960.6,1688.41 -2947.29,1688.41 -2939.29,1680.41 v1(-2937.01,1680.41)
  L6-BOT w3.3: v1(-3614.17,2060.05) -3611.89,2060.05 -3603.89,2068.05 -3578.44,2068.05 -3380.2,1869.82 -3380.2,1826.51 -3342.78,1789.09 -3307.09,1789.09 -3299.47,1789.09 -3279.78,1769.4 -3206.11,1769.4 -3125.13,1688.41 -2947.29,1688.41 -2939.29,1680.41 v1(-2937.01,1680.41)
QSFP_2_TX4_N: J9.5 MC1.34 | length 1276.7
  L1-TOP w3.3: v1(-3040.16,1646.36) -3037.87,1646.36 -3029.87,1638.36 -3024.61,1638.36 -3016.56,1638.36 -3011.22,1643.7 MC1.34@-2988.58,1643.7
  L6-BOT w3.3: v2(-3977.59,2161.25) -3975.45,2161.25 -3968.31,2154.11 -3863.4,2154.11 -3813.9,2104.61 -3743.84,2104.61 -3551.48,1912.26 -3476.84,1912.26 -3418.45,1853.86 -3418.45,1747.57 -3366.61,1695.73 -3307.09,1695.73 -3189.59,1695.73 -3132.22,1638.36 -3050.44,1638.36 -3042.44,1646.36 v1(-3040.16,1646.36)
QSFP_2_TX4_P: J9.6 MC1.32 | length 1276.7
  L1-TOP w3.3: v1(-3040.16,1621.36) -3037.87,1621.36 -3029.87,1629.36 -3020.88,1629.36 -3016.56,1629.36 -3011.22,1624.02 MC1.32@-2988.58,1624.02
  L6-BOT w3.3: v2(-3977.59,2137.96) -3975.45,2137.96 -3968.31,2145.11 -3867.13,2145.11 -3817.63,2095.61 -3747.57,2095.61 -3555.21,1903.26 -3480.57,1903.26 -3427.45,1850.14 -3427.45,1743.84 -3370.34,1686.73 -3307.09,1686.73 -3193.32,1686.73 -3135.95,1629.36 -3050.44,1629.36 -3042.44,1621.36 v1(-3040.16,1621.36)
QSFP_3_INT_B_3V3: J30.28 R42.1 U5.15 | length 7101.7
  L1-TOP w5: J30.28@716.14,1580.71 754.57,1580.71 765.39,1569.89 765.39,1529.39 776.98,1517.81 v1(1009.52,1517.81)
  L1-TOP w6: U5.15@-3661.42,3255.91 -3661.42,3293.23 -3645.99,3308.65 -3645.99,3315.99 -3639.15,3322.83 v1(-3637.8,3322.83)
  L4-PWR w6: v1(-3637.8,3322.83) -3637.8,3144.1 -3131.1,2637.4 -2906.42,2637.4 -764.64,495.62 558.45,495.62 642.18,579.35 642.18,958.55 984.7,1301.07 984.7,1408.21 1009.52,1433.04 v1(1009.52,1517.81)
QSFP_3_INT_B_VIO: MC1.121 R40.1 U5.4 | length 539.8
  L1-TOP w6: U5.4@-3661.42,3094.49 -3661.42,3062.99 -3647.64,3049.21 v1(-3647.64,3027.56) ; v1(-3281.5,2903.54) MC1.121@-3231.89,2903.54
  L6-BOT w6: v1(-3647.64,3027.56) -3484.25,3027.56 -3360.24,2903.54 v1(-3281.5,2903.54)
QSFP_3_LP_MODE_3V3: J30.31 R43.1 U5.11 | length 6638.3
  L1-TOP w5: J30.31@716.14,1486.22 716.89,1486.97 890.98,1486.97 913.39,1464.57 v1(952.76,1464.57)
  L1-TOP w6: U5.11@-3590.55,3204.72 -3559.06,3204.72 -3545.28,3190.94 v1(-3521.65,3190.94)
  L4-PWR w6: v1(-3521.65,3190.94) -3521.65,3092.52 -3149.61,2720.47 -2925.2,2720.47 -741.99,537.26 541.2,537.26 600.53,596.6 600.53,975.8 943.05,1318.32 943.05,1419.82 952.76,1429.52 v1(952.76,1464.57)
QSFP_3_LP_MODE_VIO: MC1.133 R36.1 U5.8 | length 450.8
  L1-TOP w6: U5.8@-3590.55,3145.67 -3562.99,3145.67 -3553.15,3155.51 R36.1@-3521.65,3155.51 ; R36.1@-3521.65,3153.54 -3501.74,3133.63 -3501.74,3076.54 -3446.85,3021.65 MC1.133@-3231.89,3021.65
QSFP_3_MODPRS_B_3V3: J30.27 R46.1 U5.14 | length 7108.2
  L1-TOP w5: J30.27@716.14,1612.2 977.62,1612.2 990.78,1625.36 v1(990.78,1626.1)
  L1-TOP w6: U5.14@-3641.73,3255.91 -3641.73,3287.4 -3627.95,3301.18 -3607.77,3301.18 -3602.36,3306.59 v1(-3602.36,3322.83)
  L4-PWR w6: v1(-3602.36,3322.83) -3602.36,3128.35 -3125.75,2651.73 -2901.07,2651.73 -758.87,509.54 552.68,509.54 628.26,585.11 628.26,964.32 970.78,1306.84 970.78,1412.93 990.78,1432.93 v1(990.78,1626.1)
QSFP_3_MODPRS_B_VIO: MC1.123 R39.1 U5.5 | length 500.7
  L1-TOP w6: U5.5@-3641.73,3094.49 -3641.73,3072.4 -3612.2,3042.87 R39.1@-3612.2,3027.56 ; R39.1@-3610.24,3027.56 -3590.55,3007.87 -3503.94,3007.87 -3419.29,2923.23 MC1.123@-3231.89,2923.23
QSFP_3_MODSEL_B_3V3: J30.8 R47.1 U5.12 | length 6519.7
  L1-TOP w5: J30.8@814.96,1501.97 911.42,1501.97 v2(921.26,1492.13)
  L1-TOP w6: U5.12@-3590.55,3224.41 -3523.62,3224.41 v1(-3521.65,3226.38)
  L4-PWR w6: v1(-3521.65,3226.38) -3500,3204.72 -3500,3158.82 -3500.28,3158.53 -3500.28,3090.83 -3145.67,2736.22 -2921.26,2736.22 -736.22,551.18 535.43,551.18 586.61,602.36 586.61,981.57 929.13,1324.09 929.13,1420 921.26,1427.88 v2(921.26,1492.13)
QSFP_3_MODSEL_B_VIO: MC1.127 R37.1 U5.7 | length 454
  L1-TOP w6: U5.7@-3590.55,3125.98 -3559.06,3125.98 -3553.15,3120.08 R37.1@-3521.65,3120.08 -3521.65,3072.83 -3411.42,2962.6 MC1.127@-3231.89,2962.6
QSFP_3_RESET_B_3V3: J30.9 R80.1 U5.13 | length 6862.8
  L1-TOP w5: J30.9@814.96,1533.46 962.6,1533.46 v2(972.44,1543.31)
  L1-TOP w6: U5.13@-3622.05,3255.91 -3622.05,3279.53 -3614.23,3287.34 -3582.06,3287.34 -3566.93,3302.47 v1(-3566.93,3322.83)
  L4-PWR w6: v1(-3566.93,3322.83) -3566.93,3112.6 -3120.01,2665.68 -2893.87,2665.68 -751.65,523.46 546.92,523.46 614.34,590.88 614.34,970.09 956.86,1312.6 956.86,1416.92 972.44,1432.5 v2(972.44,1543.31)
QSFP_3_RESET_B_VIO: MC1.125 R38.1 U5.6 | length 475.5
  L1-TOP w6: U5.6@-3622.05,3094.49 -3622.05,3081.5 -3607.48,3066.93 -3590.55,3066.93 -3576.77,3053.15 R38.1@-3576.77,3027.56 -3500,3027.56 -3415.35,2942.91 MC1.125@-3231.89,2942.91
QSFP_3_RX1_N: J30.18 MC2.43 | length 1381
  L6-BOT w3.3: v1(-389.76,2138.48) -387.48,2138.48 -379.48,2130.48 -341.14,2130.48 -283.77,2073.12 -212.5,2073.12 -165.26,2025.87 -61.42,2025.87 441.04,2025.87 661.23,1805.68 841.14,1805.68 848.29,1812.83 v2(850.43,1812.83)
QSFP_3_RX1_P: J30.17 MC2.41 | length 1381
  L6-BOT w3.3: v1(-389.76,2113.48) -387.48,2113.48 -379.48,2121.48 -344.87,2121.48 -287.5,2064.12 -216.23,2064.12 -168.99,2016.87 -61.42,2016.87 437.31,2016.87 657.5,1796.68 841.14,1796.68 848.29,1789.54 v2(850.43,1789.54)
QSFP_3_RX2_N: J30.21 MC2.39 | length 1301.1
  L1-TOP w3.3: MC2.39@-357.87,1879.92 -335.24,1879.92 -329.89,1874.58 -224.86,1874.58 -212.12,1887.31 -212.12,1943.93 -149.86,2006.19 -61.42,2006.19 23.72,2006.19 288.99,1740.92 380.3,1740.92 429.32,1789.93 680.43,1789.93 682.36,1791.87 682.36,1795.94 687.6,1801.18 J30.21@716.14,1801.18
QSFP_3_RX2_P: J30.22 MC2.37 | length 1301.1
  L1-TOP w3.3: MC2.37@-357.87,1860.24 -335.24,1860.24 -329.89,1865.58 -221.13,1865.58 -203.12,1883.59 -203.12,1940.2 -146.14,1997.19 -61.42,1997.19 19.99,1997.19 285.26,1731.92 384.03,1731.92 433.05,1780.93 680.43,1780.93 682.36,1779 682.36,1774.92 687.6,1769.68 J30.22@716.14,1769.68
QSFP_3_RX3_N: J30.15 MC2.35 | length 1421.5
  L6-BOT w3.3: v1(-389.76,1823.52) -387.48,1823.52 -379.48,1815.52 -341.31,1815.52 -284.51,1872.33 -185.3,1872.33 -82.93,1974.69 -61.42,1974.69 378.21,1974.69 641.71,1711.19 841.14,1711.19 848.29,1718.34 v2(850.43,1718.34)
QSFP_3_RX3_P: J30.14 MC2.33 | length 1421.5
  L6-BOT w3.3: v1(-389.76,1798.52) -387.48,1798.52 -379.48,1806.52 -337.59,1806.52 -280.78,1863.33 -181.57,1863.33 -79.21,1965.69 -61.42,1965.69 374.48,1965.69 637.98,1702.19 841.14,1702.19 848.29,1695.05 v2(850.43,1695.05)
QSFP_3_RX4_N: J30.24 MC2.31 | length 1178
  L1-TOP w3.3: v1(358.27,1672.23) 360.55,1672.23 368.55,1664.23 418.06,1664.23 473.67,1719.84 635.99,1719.84 660.39,1695.44 680.43,1695.44 682.36,1697.38 682.36,1701.45 687.6,1706.69 J30.24@716.14,1706.69
  L6-BOT w3.3: v1(-325.98,1764.47) -323.7,1764.47 -315.7,1756.47 -283.57,1756.47 -250.39,1789.65 -180.68,1789.65 -156.5,1813.84 -61.42,1813.84 113.87,1813.84 263.48,1664.23 347.98,1664.23 355.98,1672.23 v1(358.27,1672.23)
QSFP_3_RX4_P: J30.25 MC2.29 | length 1178
  L1-TOP w3.3: v1(358.27,1647.23) 360.55,1647.23 368.55,1655.23 421.78,1655.23 477.4,1710.84 632.26,1710.84 656.66,1686.44 680.43,1686.44 682.36,1684.51 682.36,1680.44 687.6,1675.2 J30.25@716.14,1675.2
  L6-BOT w3.3: v1(-325.98,1739.47) -323.7,1739.47 -315.7,1747.47 -279.84,1747.47 -246.66,1780.65 -176.95,1780.65 -152.77,1804.84 -61.42,1804.84 110.14,1804.84 259.75,1655.23 347.98,1655.23 355.98,1647.23 v1(358.27,1647.23)
QSFP_3_SCL_3V3: J30.11 R81.1 U8.18 | length 10471.6
  L1-TOP w5: J30.11@814.96,1596.46 815.94,1597.44 1207.68,1597.44 v2(1208.66,1598.43)
  L1-TOP w6: v1(-4407.48,3324.8) -4405.51,3324.8 -4383.86,3303.15 U8.18@-4383.86,3257.87
  L4-PWR w6: v1(-4407.48,3324.8) -4431.1,3301.18 -4539.58,3301.18 -4660.51,3180.25 -4660.51,2502.75 -4902.24,2261.01 -4902.24,1543.92 -4672.32,1313.99 -4672.32,739.26 -4305.1,372.03 610.32,372.03 764.45,526.16 764.45,908.05 891.16,1034.77 1091.95,1034.77 1236.89,1179.71 1236.89,1343.73 1208.66,1371.96 v2(1208.66,1598.43)
QSFP_3_SCL_VIO: MC1.131 R62.1 U8.1 | length 1793.9
  L1-TOP w6: v1(-4407.48,3029.53) -4407.48,3049.21 -4383.86,3072.83 U8.1@-4383.86,3096.46 ; v1(-3281.5,3001.97) MC1.131@-3231.89,3001.97
  L6-BOT w6: v1(-4407.48,3029.53) -4325.97,2948.02 -4150.74,2948.02 -3948.58,3150.18 -3948.58,3299.69 -3849.67,3398.6 -3580.09,3398.6 -3346.46,3164.96 -3346.46,3046.61 -3301.81,3001.97 v1(-3281.5,3001.97)
QSFP_3_SDA_3V3: J30.12 R82.1 U8.19 | length 10621.8
  L1-TOP w5: J30.12@814.96,1627.95 946.85,1627.95 968.5,1649.61 v2(1208.66,1649.61)
  L1-TOP w6: v1(-4442.91,3324.8) -4442.91,3234.25 -4435.04,3226.38 U8.19@-4415.35,3226.38
  L4-PWR w6: v1(-4442.91,3324.8) -4462.6,3324.8 -4469.56,3317.84 -4546.48,3317.84 -4677.17,3187.15 -4677.17,2509.65 -4918.9,2267.91 -4918.9,1537.02 -4688.98,1307.09 -4688.98,732.36 -4312,355.38 617.22,355.38 781.11,519.26 781.11,901.15 898.06,1018.11 1098.85,1018.11 1253.55,1172.81 1253.55,1350.69 1232.28,1371.96 1232.28,1625.98 v2(1208.66,1649.61)
QSFP_3_SDA_VIO: MC1.129 R63.1 U8.24 | length 1879.6
  L1-TOP w6: v1(-4442.91,3029.53) -4442.91,3116.48 -4433.17,3126.23 -4417.08,3126.23 U8.24@-4415.35,3127.95 ; v1(-3305.12,2982.28) MC1.129@-3231.89,2982.28
  L6-BOT w6: v1(-4442.91,3029.53) -4344.44,2931.05 -4143.85,2931.05 -3931.71,3143.19 -3931.71,3292.7 -3842.68,3381.73 -3587.08,3381.73 -3365.26,3159.91 -3365.26,3042.43 v1(-3305.12,2982.28)
QSFP_3_TX1_N: J30.37 MC2.44 | length 1531.3
  L1-TOP w3.3: MC2.44@-114.57,2135.83 -91.93,2135.83 -86.59,2130.48 -61.42,2130.48 13.76,2130.48 329.04,1815.2 342.41,1801.83 353.72,1801.83 v1(355.34,1800.22) ; v1(377.03,1424.27) 378.64,1422.66 389.96,1422.66 405.98,1406.64 461.28,1406.64 501.98,1365.94 501.98,1334.94 557.68,1279.25 633.95,1279.25 663.2,1308.49 680.43,1308.49 682.36,1306.56 682.36,1302.48 687.6,1297.24 J30.37@716.14,1297.24
  L6-BOT w3.3: v1(355.34,1800.22) 356.95,1798.6 356.95,1787.29 367.68,1776.56 447.13,1697.11 447.13,1432.81 430.35,1416.03 396.58,1416.03 389.96,1422.66 378.64,1422.66 v1(377.03,1424.27)
QSFP_3_TX1_P: J30.36 MC2.42 | length 1526.9
  L1-TOP w3.3: MC2.42@-114.57,2116.14 -91.93,2116.14 -86.59,2121.48 10.03,2121.48 19.19,2112.32 40.37,2091.14 cw(c36.37,2087.14) 40.37,2083.14 30.7,2073.47 ccw(c34.7,2069.46) 30.7,2065.46 42.7,2053.45 ccw(c46.7,2057.46) 50.71,2053.45 60.38,2063.13 cw(c64.38,2059.13) 68.38,2063.13 82.39,2049.12 325.32,1806.2 336.04,1795.47 336.04,1784.15 v1(337.66,1782.54) ; v1(394.71,1441.95) 396.32,1440.34 396.32,1429.02 409.71,1415.64 465.01,1415.64 510.98,1369.67 510.98,1338.67 561.4,1288.25 630.23,1288.25 659.47,1317.49 680.43,1317.49 682.36,1319.43 682.36,1323.5 687.6,1328.74 J30.36@716.14,1328.74
  L6-BOT w3.3: v1(337.66,1782.54) 339.27,1780.93 350.59,1780.93 363.95,1767.56 438.13,1693.38 438.13,1436.54 426.62,1425.03 400.31,1425.03 396.32,1429.02 396.32,1440.34 v1(394.71,1441.95)
QSFP_3_TX2_N: J30.2 MC2.40 | length 1436.9
  L6-BOT w3.3: v1(-82.68,1882.58) -80.39,1882.58 -72.39,1874.58 -61.42,1874.58 360.05,1874.58 523.66,1710.97 523.66,1592.86 633.39,1483.13 744.4,1483.13 770.22,1508.94 859.71,1508.94 909.89,1458.76 909.89,1356.2 877.93,1324.24 859.71,1324.24 852.56,1317.09 v2(850.43,1317.09)
QSFP_3_TX2_P: J30.3 MC2.38 | length 1436.9
  L6-BOT w3.3: v1(-82.68,1857.58) -80.39,1857.58 -72.39,1865.58 -61.42,1865.58 356.32,1865.58 514.66,1707.24 514.66,1589.13 551.9,1551.9 573.07,1530.72 cw(c569.07,1526.72) 573.07,1522.71 567.1,1516.74 ccw(c571.1,1512.74) 567.1,1508.73 579.11,1496.73 ccw(c583.11,1500.73) 587.11,1496.73 593.08,1502.7 cw(c597.09,1498.7) 601.09,1502.7 617.03,1486.76 629.66,1474.13 748.13,1474.13 773.94,1499.94 855.98,1499.94 900.89,1455.04 900.89,1359.92 874.2,1333.24 859.71,1333.24 852.56,1340.39 v2(850.43,1340.39)
QSFP_3_TX3_N: J30.34 MC2.36 | length 1295.9
  L1-TOP w3.3: MC2.36@-114.57,1820.87 -137.2,1820.87 -142.55,1815.52 -153.08,1815.52 -166.48,1828.93 -166.48,1902.04 -121.95,1946.57 -43.2,1946.57 -16.82,1920.19 4.36,1899.01 cw(c0.35,1895.01) 4.36,1891 -1.62,1885.03 ccw(c2.38,1881.03) -1.62,1877.02 10.39,1865.02 ccw(c14.39,1869.02) 18.39,1865.02 24.37,1870.99 cw(c28.37,1866.99) 32.37,1870.99 49.36,1854.01 366.81,1536.56 516.24,1536.56 649.82,1402.98 680.43,1402.98 682.36,1401.05 682.36,1396.97 687.6,1391.73 J30.34@716.14,1391.73
QSFP_3_TX3_P: J30.33 MC2.34 | length 1295.9
  L1-TOP w3.3: MC2.34@-114.57,1801.18 -137.2,1801.18 -142.55,1806.52 -156.81,1806.52 -175.48,1825.2 -175.48,1905.77 -125.68,1955.57 -61.42,1955.57 -39.47,1955.57 370.54,1545.56 519.97,1545.56 653.55,1411.98 680.43,1411.98 682.36,1413.91 682.36,1417.99 687.6,1423.23 J30.33@716.14,1423.23
QSFP_3_TX4_N: J30.5 MC2.32 | length 1261.9
  L6-BOT w3.3: v1(-82.68,1764.47) -84.96,1764.47 -92.96,1756.47 -116.12,1756.47 -140.05,1732.54 -140.05,1700.53 -109.85,1670.34 -61.42,1670.34 16.3,1670.34 327.24,1359.39 475.91,1359.39 535.25,1418.73 841.14,1418.73 848.29,1411.58 v2(850.43,1411.58)
QSFP_3_TX4_P: J30.6 MC2.30 | length 1261.9
  L6-BOT w3.3: v1(-82.68,1739.47) -84.96,1739.47 -92.96,1747.47 -112.39,1747.47 -131.05,1728.81 -131.05,1704.26 -106.12,1679.34 -61.42,1679.34 20.02,1679.34 58.34,1641.02 72.14,1627.22 ccw(c76.14,1631.22) 80.14,1627.22 86.12,1633.19 cw(c90.12,1629.19) 94.12,1633.19 106.13,1621.19 cw(c102.13,1617.19) 106.13,1613.18 100.15,1607.21 ccw(c104.16,1603.21) 100.15,1599.2 121.33,1578.03 330.97,1368.39 472.18,1368.39 531.52,1427.73 841.14,1427.73 848.29,1434.87 v2(850.43,1434.87)
QSFP_4_INT_B_3V3: J31.28 R45.1 U8.17 | length 11582.3
  L1-TOP w5: J31.28@716.14,2564.96 754.57,2564.96 765.39,2554.14 765.39,2513.65 776.97,2502.07 1176.47,2502.07 v1(1176.9,2502.51)
  L1-TOP w6: v1(-4372.05,3324.8) -4371.02,3324.8 -4364.17,3317.96 U8.17@-4364.17,3257.87
  L4-PWR w6: v1(-4372.05,3324.8) -4411.42,3285.43 -4533.06,3285.43 -4644.76,3173.73 -4644.76,2496.23 -4886.49,2254.49 -4886.49,1550.44 -4656.57,1320.52 -4656.57,745.78 -4298.57,387.78 603.79,387.78 748.7,532.69 748.7,914.58 884.64,1050.51 1085.42,1050.51 1221.14,1186.23 1221.14,1336.68 1177.83,1379.99 1177.83,1732.12 1331.38,1885.67 1331.38,2240.32 1176.9,2394.79 v1(1176.9,2502.51)
QSFP_4_INT_B_VIO: MC1.135 R61.1 U8.2 | length 1737.4
  L1-TOP w6: v1(-4372.05,3029.53) -4372.05,3053.15 -4364.17,3061.02 U8.2@-4364.17,3096.46 ; v1(-3281.5,3041.34) MC1.135@-3231.89,3041.34
  L6-BOT w6: v1(-4372.05,3029.53) -4305.88,2963.36 -4159.86,2963.36 -3965.87,3157.35 -3965.87,3306.86 -3856.83,3415.9 -3572.93,3415.9 -3326.77,3169.74 -3326.77,3051.18 -3316.93,3041.34 v1(-3281.5,3041.34)
QSFP_4_LP_MODE_3V3: J31.31 R52.1 U8.13 | length 11196.7
  L1-TOP w5: J31.31@716.14,2470.47 716.89,2471.22 1048.46,2471.22 v1(1066.93,2452.76)
  L1-TOP w6: U8.13@-4285.43,3257.87 -4285.43,3281.5 -4277.62,3289.31 -4245.44,3289.31 -4230.32,3304.44 v1(-4230.32,3324.8)
  L4-PWR w6: v1(-4230.32,3324.8) -4230.32,3261.81 -4405.51,3086.61 -4519.68,3086.61 -4581.1,3025.2 -4581.1,2471.02 -4822.83,2229.29 -4822.83,1576.81 -4592.91,1346.88 -4592.91,772.15 -4272.2,451.44 577.43,451.44 685.04,559.06 685.04,940.94 858.27,1114.17 1059.06,1114.17 1157.48,1212.6 1157.48,1311.34 1110.86,1357.96 1110.86,1760.59 1181.1,1830.84 1181.1,2253.28 1053.54,2380.84 1053.54,2439.37 v1(1066.93,2452.76)
QSFP_4_LP_MODE_VIO: MC1.58 R57.1 U8.6 | length 2966.1
  L1-TOP w6: U8.6@-4285.43,3096.46 -4285.43,3083.46 -4276.77,3074.8 -4248.03,3074.8 -4230.31,3057.09 v1(-4230.31,3029.53) ; v1(-3157.48,3074.8) -3157.48,2956.69 -3137.8,2937.01 -3074.8,2937.01 -3055.12,2917.32 -3055.12,1901.57 -3033.46,1879.92 MC1.58@-2988.58,1879.92
  L6-BOT w6: v1(-4230.31,3029.53) -4186.5,3029.53 -4031.5,3184.53 -4031.5,3334.04 -3884.02,3481.52 -3545.75,3481.52 -3185.99,3121.76 -3178.2,3121.76 -3157.48,3101.05 v1(-3157.48,3074.8)
QSFP_4_MODPRS_B_3V3: J31.27 R44.1 U8.16 | length 11556.1
  L1-TOP w5: J31.27@716.14,2596.46 1135.83,2596.46 v1(1153.54,2578.74)
  L1-TOP w6: U8.16@-4344.49,3257.87 -4344.49,3317.96 -4337.65,3324.8 v1(-4336.61,3324.8)
  L4-PWR w6: v1(-4336.61,3324.8) -4392.4,3269.02 -4526.26,3269.02 -4628.34,3166.93 -4628.34,2489.43 -4870.08,2247.69 -4870.08,1557.24 -4640.15,1327.32 -4640.15,752.58 -4291.77,404.2 596.99,404.2 732.28,539.49 732.28,921.38 877.84,1066.93 1078.62,1066.93 1204.72,1193.03 1204.72,1329.88 1161.42,1373.19 1161.42,1738.92 1314.96,1892.47 1314.96,2233.52 1153.54,2394.94 v1(1153.54,2578.74)
QSFP_4_MODPRS_B_VIO: MC1.137 R60.1 U8.3 | length 1690.8
  L1-TOP w6: U8.3@-4344.49,3096.46 -4344.49,3064.96 -4336.61,3057.09 v1(-4336.61,3029.53) ; v1(-3305.12,3061.02) MC1.137@-3231.89,3061.02
  L6-BOT w6: v1(-4336.61,3029.53) -4285.06,2977.98 -4168.75,2977.98 -3982.5,3164.23 -3982.5,3313.74 -3863.72,3432.52 -3566.04,3432.52 -3307.09,3173.56 -3305.12,3171.59 v1(-3305.12,3061.02)
QSFP_4_MODSEL_B_3V3: J31.8 R53.1 U8.14 | length 11235.6
  L1-TOP w5: J31.8@814.96,2486.22 1096.46,2486.22 v2(1110.24,2472.44)
  L1-TOP w6: U8.14@-4305.12,3257.87 -4305.12,3289.37 -4291.34,3303.15 -4271.16,3303.15 -4265.75,3308.56 v1(-4265.75,3324.8)
  L4-PWR w6: v1(-4265.75,3324.8) -4265.75,3250 -4413.39,3102.36 -4527.56,3102.36 -4596.85,3033.07 -4596.85,2476.38 -4838.58,2234.65 -4838.58,1570.29 -4608.66,1340.36 -4608.66,765.62 -4278.73,435.69 583.95,435.69 700.79,552.53 700.79,934.42 864.79,1098.43 1065.58,1098.43 1173.23,1206.08 1173.23,1316.84 1129.92,1360.14 1129.92,1751.97 1283.46,1905.51 1283.46,2220.47 1110.24,2393.7 v2(1110.24,2472.44)
QSFP_4_MODSEL_B_VIO: MC1.141 R58.1 U8.5 | length 1665
  L1-TOP w6: U8.5@-4305.12,3096.46 -4305.12,3076.77 -4291.34,3062.99 -4271.65,3062.99 -4265.75,3057.09 v1(-4265.75,3029.53) ; MC1.141@-3231.89,3100.39 v1(-3182.28,3100.39)
  L6-BOT w6: v1(-4265.75,3029.53) -4244.09,3007.87 -4185.23,3007.87 -4015.29,3177.81 -4015.29,3327.32 -3877.3,3465.31 -3552.46,3465.31 -3307.09,3219.94 -3192.35,3105.2 -3190.88,3105.2 -3186.07,3100.39 v1(-3182.28,3100.39)
QSFP_4_RESET_B_3V3: J31.9 R83.1 U8.15 | length 11339.2
  L1-TOP w5: J31.9@814.96,2517.72 1116.14,2517.72 v2(1129.92,2531.5)
  L1-TOP w6: U8.15@-4324.8,3257.87 -4324.8,3295.2 -4309.38,3310.62 -4309.38,3317.96 -4302.54,3324.8 v1(-4301.18,3324.8)
  L4-PWR w6: v1(-4301.18,3324.8) -4301.18,3238.19 -4421.26,3118.11 -4535.43,3118.11 -4612.6,3040.95 -4612.6,2482.9 -4854.33,2241.17 -4854.33,1563.76 -4624.41,1333.84 -4624.41,759.1 -4285.25,419.95 590.47,419.95 716.54,546.01 716.54,927.9 871.31,1082.68 1072.1,1082.68 1188.98,1199.55 1188.98,1323.36 1145.67,1366.67 1145.67,1745.45 1299.21,1898.99 1299.21,2227 1129.92,2396.29 v2(1129.92,2531.5)
QSFP_4_RESET_B_VIO: MC1.139 R59.1 U8.4 | length 1644.7
  L1-TOP w6: U8.4@-4324.8,3096.46 -4324.8,3068.9 -4301.18,3045.28 v1(-4301.18,3029.53) ; v1(-3281.5,3080.71) MC1.139@-3231.89,3080.71
  L6-BOT w6: v1(-4301.18,3029.53) -4264.61,2992.95 -4178.31,2992.95 -3999.85,3171.42 -3999.85,3320.93 -3870.91,3449.87 -3558.85,3449.87 -3307.09,3198.1 -3281.5,3172.51 v1(-3281.5,3080.71)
